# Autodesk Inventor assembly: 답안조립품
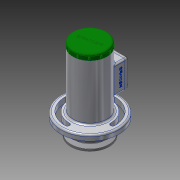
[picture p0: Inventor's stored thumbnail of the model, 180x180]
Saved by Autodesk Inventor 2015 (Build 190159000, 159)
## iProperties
Created: 2017-05
Part Number: 답안조립품
Document SubType Name: Assembly
Designer: user
Author: user
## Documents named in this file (20)
- C:\Users\user\Desktop\470507V1001\답안조립품.iam
- C:\Users\user\Desktop\470507V1001\1.본체.ipt
- C:\Users\user\Desktop\470507V1001\V-벨트풀리.ipt
- C:\Users\user\Desktop\470507V1001\너트 M10.ipt
- C:\Users\user\Desktop\470507V1001\멈춤링 15 x 1.ipt
- C:\Users\user\Desktop\470507V1001\멈춤링 35x1.6.ipt
- C:\Users\user\Desktop\470507V1001\베어링 15 x 35 x 11.ipt
- C:\Users\user\Desktop\470507V1001\볼트 M4 x 10.ipt
- C:\Users\user\Desktop\470507V1001\부시1.ipt
- C:\Users\user\Desktop\470507V1001\부시2.ipt
- C:\Users\user\Desktop\470507V1001\사이드 커버.ipt
- 사이드 커버.ipt
- C:\Users\user\Desktop\470507V1001\십자볼트 M3 x 10.ipt
- C:\Users\user\Desktop\470507V1001\오일 실 15 25 7.ipt
- C:\Users\user\Desktop\470507V1001\와셔 3x6.ipt
- C:\Users\user\Desktop\470507V1001\와셔 4x16.ipt
- C:\Users\user\Desktop\470507V1001\와셔 10x21.ipt
- C:\Users\user\Desktop\470507V1001\축.ipt
- C:\Users\user\Desktop\470507V1001\키 4 x 4 x 18.ipt
- C:\Users\user\Desktop\470507V1001\탑 커버.ipt
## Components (3 placed, 3 different names)
1. 1.본체:1
2. V-벨트풀리:1
3. ISO 4017 M4 x 10:1
